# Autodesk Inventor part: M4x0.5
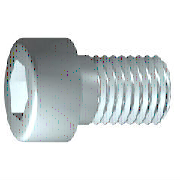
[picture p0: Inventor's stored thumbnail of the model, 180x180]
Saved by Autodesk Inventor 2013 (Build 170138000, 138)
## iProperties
IsCustomPart: 1
Company: 한국ATC센터
Created: 2009-02
Part Number: M4x0.5
Material: 강, 연강
Description: 6각머리 태핑 나사
Document SubType Name: Modeling
Standard: KS B 1003
Designer: KYOUNG IL JANG
Standards Organization: KS
Language: ko-KR
Size Designation: M 4 x 12
Categories: <MemberInstance><Categories><Category DisplayName="조임쇠" InternalName="e4da775c-781d-43d5-af7c-5136215cf5a6" Mnemonic="FSTN"><Category DisplayName="볼트" InternalN
Density: 1 g/cm^3
Author: KYOUNG IL JANG
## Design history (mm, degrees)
sketch "스케치1"
  geometry: L1 (-1, 0)-(12, 0); L2 (12, 0)-(12, 2); L3 (12, 2)-(1.75, 2); L4 (1.75, 2)-(1.32, 2); L5 (1.32, 2)-(0, 2); L6 (0, 2)-(0, 3.5); L7 (0, 3.5)-(-4, 3.5); L8 (-4, 3.5)-(-4, 1.732); L9 (-4, 1.732)-(-2, 1.732); L10 (-2, 1.732)-(-1, 0); L11 (-7.2, 0)-(15.2, 0) reference; L12 (0, -0.7)-(0, 4.2) reference; L13 (1.75, 2)-(0, 2)
  constraints: 22 end point, 6 parallel, 2 collinear, 2 perpendicular, 1 horizontal, 1 point on line
  dimensions: "d1" = 10.25 distance from line of L3.end L2 (= GEL); "d2" = 0.42952 distance of L4.end L3.end (computed from GAL); "d3" = 4 distance between parallel lines of L8 L6 (= KOH); "d4" = 2 distance of L8.end L9.end (= INTI); "d5" = 60 deg angle of L10 L1; "d6" = 4 diameter of L3 L1 (= GD); "d7" = 4 diameter of L5 L1 (= BDM); "d8" = 3.4641 diameter of L9 L1 (= 1.1547 x SW); "d9" = 7 diameter of L7 L1 (= KOD); "d26" = 12 distance between parallel lines of L12 L2 (= NLG)
revolve "본체" sketch "스케치1" stored, may be unused: angle "d10" = 90 deg
sketch "스케치2"
  geometry: L1 (0, -4.9)-(0, 4.9) reference; L2 (-4.9, 0)-(4.9, 0) reference; L3 (1.732, 0)-(0.866, -1.5); L4 (0.866, -1.5)-(-0.866, -1.5); L5 (-0.866, -1.5)-(-1.732, 0); L6 (-1.732, 0)-(-0.866, 1.5); L7 (-0.866, 1.5)-(0.866, 1.5); L8 (0.866, 1.5)-(1.732, 0); 2 further points
  constraints: 12 end point, 1 coincident, 1 horizontal alignment, 1 point on line, 12 other
extrude "슬롯" join sketch "스케치2" stored distance "d11" = 10; taper "d12" = 0 deg
workplane "Work Plane1"
fillet "Fillet2" dims "d30" = 0.1 (= R)
body "Solid1"
fillet "모깎기1" dims "d17" = 0.4 (= RR)
feature "스레드" dims "d13" = 10.25 (= GEL), "d14" = 0
chamfer "모따기1" distance "d15" = 0.42941 (= -0.5 x SPD + 0.5 x GD); stored, may be unused: second distance "d16" = 0.42941 (= GUL), angle "d27" = 45 deg
other parameters: "GD" = 4 (= NND) [user parameter; used in 2 equation terms], "NLG" = 12 [user parameter; used in 1 equation term], "GEL" = 10.25 [user parameter; used in 2 equation terms], "KOD" = 7 [user parameter; used in 1 equation term], "KOH" = 4 [user parameter; used in 1 equation term], "INTI" = 2 [user parameter; used in 1 equation term], "GAL" = 0.42941 (= 0.61345 x PTC) [user parameter; used in 1 equation term], "GUL" = 0.42941 (= 0.61345 x PTC) [user parameter; used in 1 equation term], "BDM" = 4 (= NND) [user parameter; used in 1 equation term], "SW" = 3 [user parameter; used in 2 equation terms], "RR" = 0.4 [user parameter; used in 1 equation term], "SPD" = 3.14117 (= NND - 1.2269 x PTC) [user parameter; used in 1 equation term], "d19" = 0, "d28" = 0, "d29" = 0, "R" = 0.1 [user parameter; used in 1 equation term], "PHH" = 0.2 [user parameter], "GD1" = 3.14117 (= THREADDIA - 1.2269 x PTC) [user parameter], "THREADDIA" = 4 [user parameter; used in 1 equation term], "FAWI" = 45 deg [user parameter], "TPU" = 14.28571 (computed from PTC) [user parameter], "PTC" = 0.7 [user parameter; used in 5 equation terms], "NND" = 4 [user parameter; used in 3 equation terms], "TOA" = 30 deg [user parameter], "E0" = 3.465 (= 1.155 x SW) [user parameter]
